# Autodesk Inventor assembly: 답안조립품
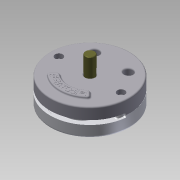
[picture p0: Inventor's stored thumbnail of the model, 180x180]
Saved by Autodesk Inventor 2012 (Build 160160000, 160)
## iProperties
Created: 2015-04
Part Number: 답안조립품
Document SubType Name: Assembly
Designer: Administrator
Author: Administrator
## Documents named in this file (6)
- C:\Documents and Settings\Administrator\바탕 화면\450405V1009\답안조립품.iam
- C:\Documents and Settings\Administrator\바탕 화면\450405V1009\본체.ipt
- C:\Documents and Settings\Administrator\바탕 화면\450405V1009\덮개.ipt
- C:\Documents and Settings\Administrator\바탕 화면\450405V1009\베어링62_22.ipt
- C:\Documents and Settings\Administrator\바탕 화면\450405V1009\축.ipt
- C:\Documents and Settings\Administrator\바탕 화면\450405V1009\멈춤링.ipt
